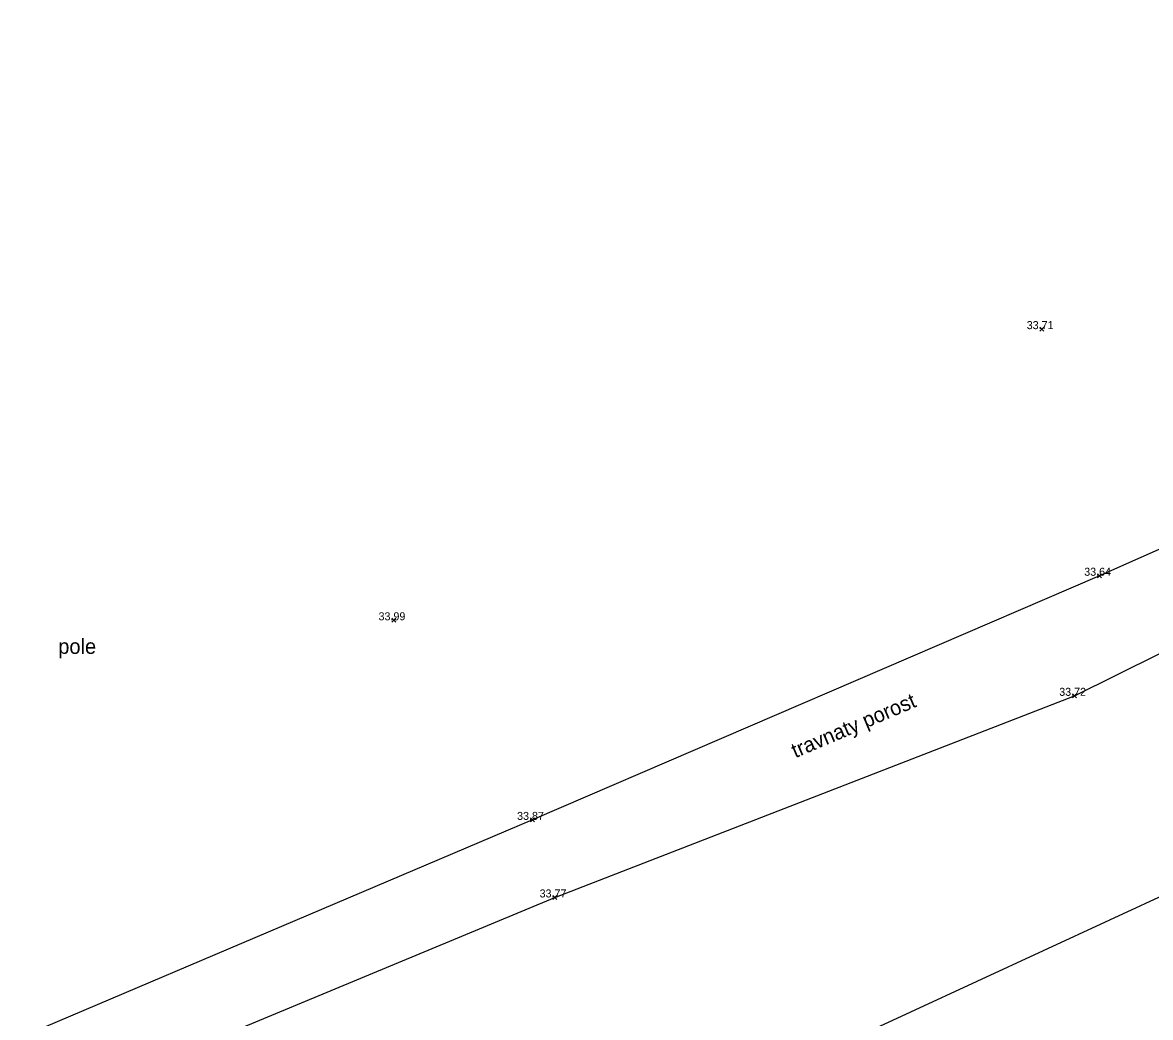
# Model space of a CAD drawing. Extents: x -772865 to -772533, y -1034366 to -1034132.
# Drawn here: x -772724.54 to -772701.99, y -1034240.85 to -1034220.96 of the extents above; entities that cross this region are included whole.
import ezdxf

# ---------------------------------------------------------------- set-up
doc = ezdxf.new("R2010")
doc.units = 0
for name, color, linetype in [('body', 7, 'Continuous'), ('KM_hranice', 7, 'Continuous'), ('mistni_popis', 7, 'Continuous'), ('oddeleni_ploch', 7, 'Continuous'), ('stromy_kere', 7, 'Continuous'), ('vyskove_koty', 7, 'Continuous')]:
    doc.layers.add(name, color=color, linetype=linetype)

msp = doc.modelspace()

# ---------------------------------------------------------------- linework, layer by layer
at = {"layer": 'body'}
for p, q in [((-772704.12, -1034227.13), (-772704.2, -1034227.05)), ((-772704.2, -1034227.13), (-772704.12, -1034227.05)), ((-772702.97, -1034232.06), (-772703.05, -1034231.98)), ((-772703.05, -1034232.06), (-772702.97, -1034231.98)), ((-772717.08, -1034232.95), (-772717.16, -1034232.87)), ((-772717.16, -1034232.95), (-772717.08, -1034232.87)), ((-772703.47, -1034234.46), (-772703.55, -1034234.38)), ((-772703.55, -1034234.46), (-772703.47, -1034234.38)), ((-772714.31, -1034236.94), (-772714.39, -1034236.86)), ((-772714.39, -1034236.94), (-772714.31, -1034236.86)), ((-772713.86, -1034238.49), (-772713.94, -1034238.41)), ((-772713.94, -1034238.49), (-772713.86, -1034238.41))]:
    msp.add_line(p, q, dxfattribs=at)
at = {"layer": 'KM_hranice'}
msp.add_line((-772692.32, -1034234.06), (-772741, -1034256.54), dxfattribs=at)
at = {"layer": 'oddeleni_ploch'}
msp.add_lwpolyline([(-772574.1, -1034196.14), (-772586.87, -1034201.34), (-772598.23, -1034205.06), (-772614.53, -1034207.42), (-772626.93, -1034206.95), (-772636.66, -1034207.26), (-772647.96, -1034208.36), (-772659.39, -1034213.08), (-772672.58, -1034218.62), (-772687.49, -1034225.14), (-772703.01, -1034232.02), (-772714.35, -1034236.9), (-772728.88, -1034243.07), (-772737.97, -1034245.74), (-772746.8, -1034246.99), (-772753.85, -1034250.11), (-772762.71, -1034257.3), (-772782.05, -1034269.18), (-772797.09, -1034276.39), (-772810.61, -1034282.39), (-772816.13, -1034284.08), (-772822.76, -1034283.4), (-772826.73, -1034280.27)], dxfattribs=at)
at = {"layer": 'stromy_kere'}
msp.add_lwpolyline([(-772765.65, -1034261.7), (-772757.35, -1034258.12), (-772757.45, -1034255.36), (-772753.97, -1034253.1), (-772751.37, -1034253.13), (-772749.46, -1034253.04), (-772745.29, -1034253.13), (-772741.93, -1034251.74), (-772739.6, -1034248.34), (-772733.8, -1034245.53), (-772729.53, -1034246.03), (-772725.99, -1034244.81), (-772724.19, -1034242.73), (-772713.9, -1034238.45), (-772703.51, -1034234.42), (-772694.98, -1034230.19)], dxfattribs=at)

# ---------------------------------------------------------------- texts
at = {"layer": 'mistni_popis'}
msp.add_text('pole', height=0.3, dxfattribs=at).set_placement((-772723.83, -1034233.581))
msp.add_text('travnaty porost', height=0.3, rotation=23.0329, dxfattribs=at).set_placement((-772709.092, -1034235.669))
at = {"layer": 'vyskove_koty'}
for s, p in [('33.71', (-772704.465, -1034227.09)), ('33.64', (-772703.315, -1034232.02)), ('33.99', (-772717.425, -1034232.91)), ('33.72', (-772703.815, -1034234.42)), ('33.87', (-772714.655, -1034236.9)), ('33.77', (-772714.205, -1034238.45))]:
    msp.add_text(s, height=0.16, dxfattribs=at).set_placement(p)

doc.saveas('drawing.dxf')
